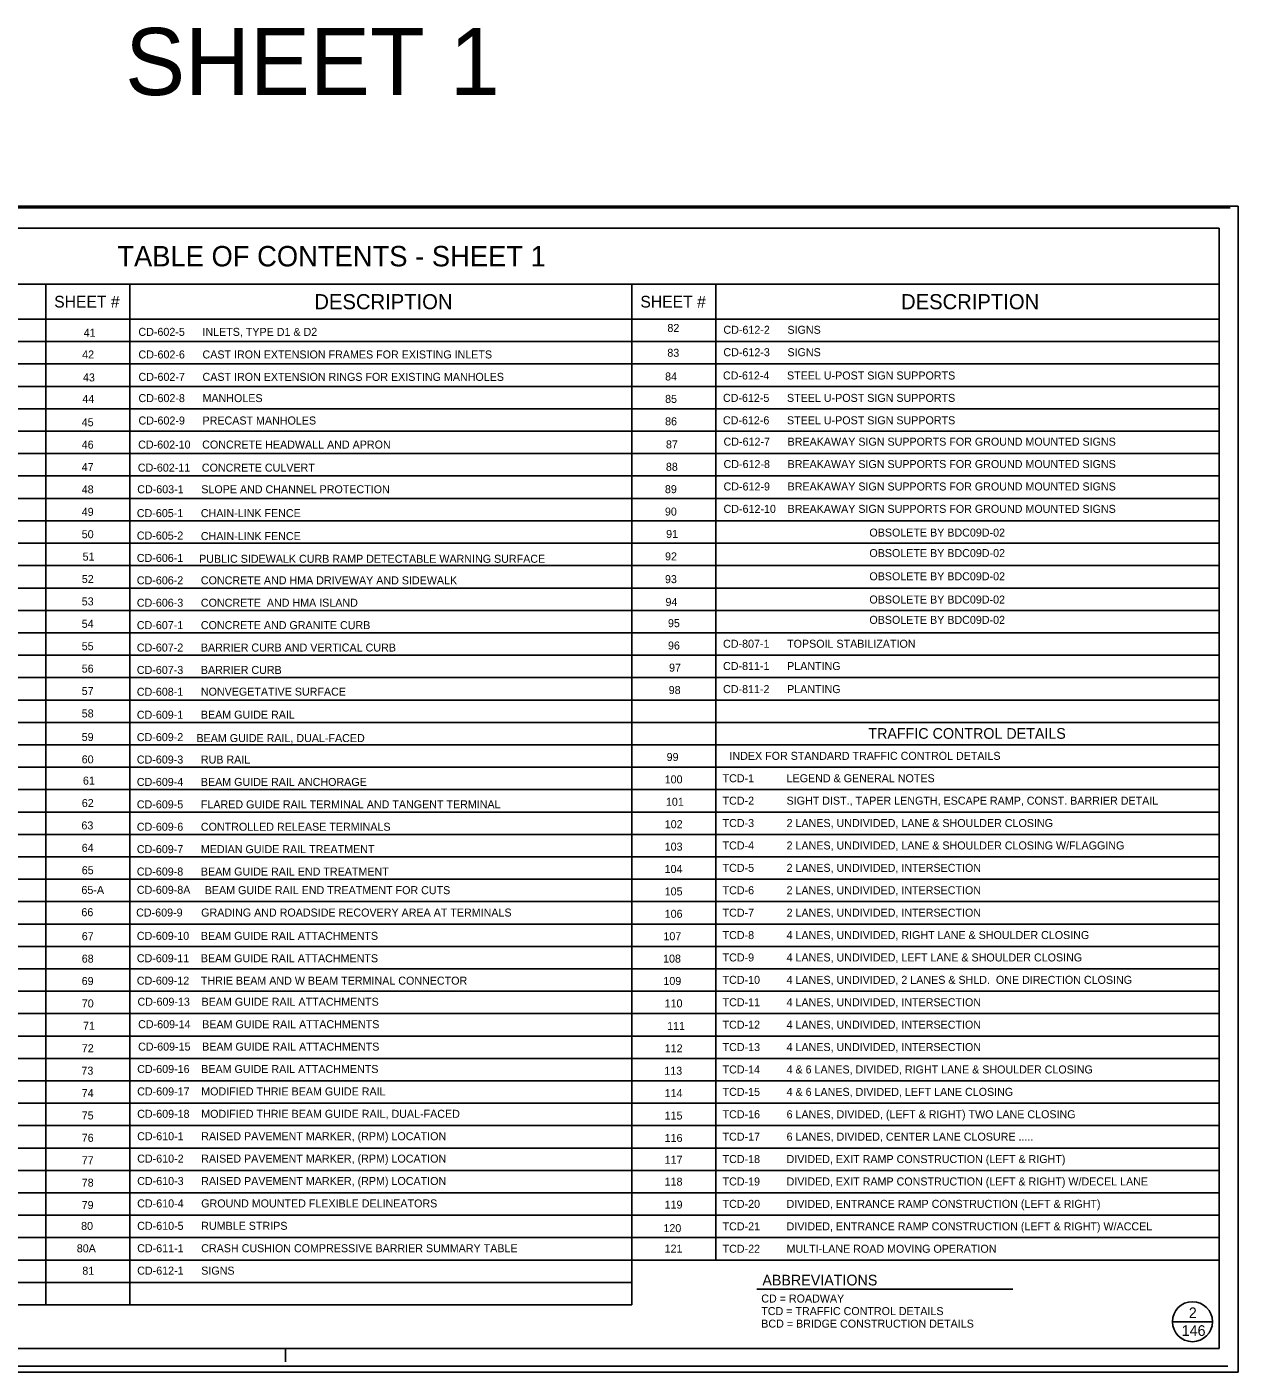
# Model space of a CAD drawing. Extents: x 499943 to 502231, y 501090 to 501849.
# Drawn here: x 500320 to 501001, y 501092 to 501849 of the extents above; entities that cross this region are included whole.
import ezdxf

# ---------------------------------------------------------------- set-up
doc = ezdxf.new("R2010")
doc.units = 0
for name, color, linetype in [('1', 7, 'Continuous'), ('39', 7, 'Continuous'), ('41', 7, 'Continuous')]:
    doc.layers.add(name, color=color, linetype=linetype)

msp = doc.modelspace()

# ---------------------------------------------------------------- linework, layer by layer
at = {"layer": '1'}
for p, q in [((500996.15, 501746.75), (499947.98, 501746.75)), ((500990, 501735.32), (500000, 501735.32)), ((500990, 501105.32), (500990, 501735.32)), ((500330.18, 501703.82), (500047.24, 501703.82)), ((500330.18, 501703.82), (500330.18, 501129.81)), ((500377.42, 501703.82), (500330.18, 501703.82)), ((500377.42, 501703.82), (500377.42, 501129.81)), ((500659.82, 501703.82), (500377.42, 501703.82)), ((500707.07, 501703.82), (500659.82, 501703.82)), ((500659.82, 501129.81), (500659.82, 501703.82)), ((500990, 501703.82), (500707.07, 501703.82)), ((500707.07, 501155), (500707.07, 501703.82)), ((500990, 501684.14), (500000, 501684.14)), ((500990, 501671.54), (500000, 501671.54)), ((500990, 501658.94), (500000, 501658.94)), ((500990, 501646.34), (500000, 501646.34)), ((500990, 501633.74), (500000, 501633.74)), ((500990, 501621.14), (500000, 501621.14)), ((500990, 501608.55), (500000, 501608.55)), ((500990, 501595.95), (500000, 501595.95)), ((500990, 501583.35), (500000, 501583.35)), ((500990, 501570.75), (500000, 501570.75)), ((500990, 501558.15), (500000, 501558.15)), ((500990, 501545.55), (500000, 501545.55)), ((500990, 501532.95), (500000, 501532.95)), ((500990, 501520.36), (500000, 501520.36)), ((500990, 501507.76), (500000, 501507.76)), ((500990, 501495.16), (500000, 501495.16)), ((500990, 501482.56), (500000, 501482.56)), ((500990, 501469.96), (500000, 501469.96)), ((500990, 501457.36), (500000, 501457.36)), ((500990, 501444.77), (500000, 501444.77)), ((500990, 501432.17), (500000, 501432.17)), ((500990, 501419.57), (500000, 501419.57)), ((500990, 501406.97), (500000, 501406.97)), ((500990, 501394.37), (500000, 501394.37)), ((500990, 501381.77), (500000, 501381.77)), ((500990, 501369.18), (500000, 501369.18)), ((500990, 501356.58), (500000, 501356.58)), ((500990, 501343.98), (500000, 501343.98)), ((500990, 501331.38), (500000, 501331.38)), ((500990, 501318.78), (500000, 501318.78)), ((500990, 501306.18), (500000, 501306.18)), ((500990, 501293.58), (500000, 501293.58)), ((500990, 501280.99), (500000, 501280.99)), ((500990, 501268.39), (500000, 501268.39)), ((500990, 501255.79), (500000, 501255.79)), ((500990, 501243.19), (500000, 501243.19)), ((500990, 501230.59), (500000, 501230.59)), ((500990, 501217.99), (500000, 501217.99)), ((500990, 501205.4), (500000, 501205.4)), ((500990, 501192.8), (500000, 501192.8)), ((500990, 501180.2), (500000, 501180.2)), ((500990, 501167.6), (500000, 501167.6)), ((500659.82, 501155), (500000, 501155)), ((500990, 501155), (500659.82, 501155)), ((500659.82, 501142.4), (500000, 501142.4)), ((500659.82, 501142.4), (500330.18, 501142.4)), ((500873.98, 501138.53), (500729.97, 501138.53)), ((500330.18, 501129.81), (500000, 501129.81)), ((500659.82, 501129.81), (500330.18, 501129.81)), ((500975, 501120.32), (500963.75, 501120.32)), ((500975, 501120.32), (500986.25, 501120.32)), ((500000, 501105.32), (500990, 501105.32)), ((500465, 501097.82), (500465, 501105.32)), ((500994.83, 501095.31), (499946.66, 501095.31))]:
    msp.add_line(p, q, dxfattribs=at)
msp.add_circle((500975, 501120.32), 11.25, dxfattribs=at)
at = {"layer": '41'}
msp.add_lwpolyline([(499942.7, 501091.97), (501000.67, 501091.97), (501000.67, 501747.65), (499942.7, 501747.65)], close=True, dxfattribs=at)

# ---------------------------------------------------------------- texts
at = {"layer": '1'}
for s, height, p in [('TABLE OF CONTENTS - SHEET 1', 11.5, (500370.42, 501713.82)), ('2', 6, (500972.96, 501122.32)), ('146', 6, (500968.97, 501112.32))]:
    msp.add_text(s, height=height, dxfattribs=at).set_placement(p)
at = {"layer": '39'}
for s, height, p in [('SHEET 1', 37.795, (500374.84, 501810.16)), ('SHEET #', 6.6, (500334.94, 501690.68)), ('DESCRIPTION', 8.5, (500481.23, 501689.73)), ('SHEET #', 6.6, (500664.58, 501690.68)), ('DESCRIPTION', 8.5, (500811.14, 501689.73)), ('41', 4.5, (500351.53, 501674.28)), ('CD-602-5', 4.5, (500382.3, 501674.76)), ('INLETS, TYPE D1 & D2', 4.5, (500418.3, 501674.76)), ('82', 4.5, (500679.77, 501676.96)), ('CD-612-2', 4.5, (500711.27, 501675.92)), ('SIGNS', 4.5, (500747.27, 501675.92)), ('42', 4.5, (500350.69, 501662.05)), ('CD-602-6', 4.5, (500382.34, 501662.05)), ('CAST IRON EXTENSION FRAMES FOR EXISTING INLETS', 4.5, (500418.34, 501662.05)), ('83', 4.5, (500679.73, 501662.99)), ('CD-612-3', 4.5, (500711.27, 501663.32)), ('SIGNS', 4.5, (500747.27, 501663.32)), ('43', 4.5, (500351.1, 501649.14)), ('CD-602-7', 4.5, (500382.34, 501649.45)), ('CAST IRON EXTENSION RINGS FOR EXISTING MANHOLES', 4.5, (500418.34, 501649.45)), ('84', 4.5, (500678.46, 501649.66)), ('CD-612-4', 4.5, (500711, 501650.22)), ('STEEL U-POST SIGN SUPPORTS', 4.5, (500747, 501650.22)), ('44', 4.5, (500350.76, 501637.05)), ('CD-602-8', 4.5, (500382.34, 501637.5)), ('MANHOLES', 4.5, (500418.34, 501637.5)), ('85', 4.5, (500678.47, 501637.06)), ('CD-612-5', 4.5, (500711, 501637.62)), ('STEEL U-POST SIGN SUPPORTS', 4.5, (500747, 501637.62)), ('45', 4.5, (500350.43, 501623.94)), ('CD-602-9', 4.5, (500382.34, 501624.9)), ('PRECAST MANHOLES', 4.5, (500418.34, 501624.9)), ('86', 4.5, (500678.47, 501624.46)), ('CD-612-6', 4.5, (500711, 501625.02)), ('STEEL U-POST SIGN SUPPORTS', 4.5, (500747, 501625.02)), ('46', 4.5, (500350.43, 501611.34)), ('CD-602-10', 4.5, (500382.17, 501611.37)), ('CONCRETE HEADWALL AND APRON', 4.5, (500418.17, 501611.37)), ('87', 4.5, (500678.95, 501611.48)), ('CD-612-7', 4.5, (500711.34, 501613)), ('BREAKAWAY SIGN SUPPORTS FOR GROUND MOUNTED SIGNS', 4.5, (500747.34, 501613)), ('47', 4.5, (500350.42, 501598.75)), ('CD-602-11', 4.5, (500381.98, 501598.4)), ('CONCRETE CULVERT', 4.5, (500417.98, 501598.4)), ('88', 4.5, (500678.93, 501598.88)), ('CD-612-8', 4.5, (500711.34, 501600.4)), ('BREAKAWAY SIGN SUPPORTS FOR GROUND MOUNTED SIGNS', 4.5, (500747.34, 501600.4)), ('48', 4.5, (500350.43, 501586.15)), ('CD-603-1', 4.5, (500381.65, 501586.23)), ('SLOPE AND CHANNEL PROTECTION', 4.5, (500417.65, 501586.23)), ('89', 4.5, (500678.36, 501586.29)), ('CD-612-9', 4.5, (500711.34, 501587.8)), ('BREAKAWAY SIGN SUPPORTS FOR GROUND MOUNTED SIGNS', 4.5, (500747.34, 501587.8)), ('49', 4.5, (500350.43, 501573.55)), ('90', 4.5, (500678.37, 501573.69)), ('CD-612-10', 4.5, (500711.34, 501575.21)), ('BREAKAWAY SIGN SUPPORTS FOR GROUND MOUNTED SIGNS', 4.5, (500747.34, 501575.21)), ('CD-605-1', 4.5, (500381.42, 501572.81)), ('CHAIN-LINK FENCE', 4.5, (500417.42, 501572.81)), ('50', 4.5, (500350.43, 501560.95)), ('CD-605-2', 4.5, (500381.42, 501560.21)), ('CHAIN-LINK FENCE', 4.5, (500417.42, 501559.89)), ('91', 4.5, (500679.05, 501561.09)), ('OBSOLETE BY BDC09D-02', 4.5, (500793.35, 501561.86)), ('51', 4.5, (500350.93, 501548.35)), ('CD-606-1', 4.5, (500381.42, 501547.61)), ('PUBLIC SIDEWALK CURB RAMP DETECTABLE WARNING SURFACE', 4.5, (500416.43, 501547.13)), ('92', 4.5, (500678.44, 501548.49)), ('OBSOLETE BY BDC09D-02', 4.5, (500793.35, 501550.34)), ('52', 4.5, (500350.47, 501535.75)), ('93', 4.5, (500678.4, 501535.69)), ('OBSOLETE BY BDC09D-02', 4.5, (500793.35, 501537.28)), ('CD-606-2', 4.5, (500381.42, 501535.02)), ('CONCRETE AND HMA DRIVEWAY AND SIDEWALK', 4.5, (500417.42, 501535.02)), ('53', 4.5, (500350.43, 501523.16)), ('CD-606-3', 4.5, (500381.42, 501522.42)), ('CONCRETE  AND HMA ISLAND', 4.5, (500417.42, 501522.42)), ('94', 4.5, (500678.69, 501522.86)), ('OBSOLETE BY BDC09D-02', 4.5, (500793.35, 501524.21)), ('OBSOLETE BY BDC09D-02', 4.5, (500793.35, 501512.78)), ('54', 4.5, (500350.42, 501510.56)), ('CD-607-1', 4.5, (500381.42, 501509.82)), ('CONCRETE AND GRANITE CURB', 4.5, (500417.42, 501509.82)), ('95', 4.5, (500680.08, 501510.93)), ('55', 4.5, (500350.43, 501497.96)), ('96', 4.5, (500680.08, 501498.34)), ('CD-807-1', 4.5, (500711.07, 501499.35)), ('TOPSOIL STABILIZATION', 4.5, (500747.07, 501499.35)), ('CD-607-2', 4.5, (500381.42, 501497.22)), ('BARRIER CURB AND VERTICAL CURB ', 4.5, (500417.42, 501497.22)), ('56', 4.5, (500350.43, 501485.36)), ('CD-607-3', 4.5, (500381.42, 501484.62)), ('BARRIER CURB', 4.5, (500417.42, 501484.62)), ('97', 4.5, (500680.7, 501485.91)), ('CD-811-1', 4.5, (500711.07, 501486.82)), ('PLANTING', 4.5, (500747.07, 501486.82)), ('57', 4.5, (500350.42, 501472.76)), ('CD-608-1', 4.5, (500381.42, 501472.34)), ('NONVEGETATIVE SURFACE', 4.5, (500417.42, 501472.4)), ('98', 4.5, (500680.5, 501473.31)), ('CD-811-2', 4.5, (500711.07, 501473.84)), ('PLANTING', 4.5, (500747.07, 501473.84)), ('58', 4.5, (500350.43, 501460.16)), ('CD-609-1', 4.5, (500381.42, 501459.42)), ('BEAM GUIDE RAIL', 4.5, (500417.42, 501459.48)), ('59', 4.5, (500350.4, 501446.91)), ('CD-609-2', 4.5, (500381.42, 501446.83)), ('BEAM GUIDE RAIL, DUAL-FACED', 4.5, (500414.94, 501446.31)), ('TRAFFIC CONTROL DETAILS', 6, (500792.79, 501448.15)), ('60', 4.5, (500350.42, 501434.32)), ('CD-609-3', 4.5, (500381.42, 501434.23)), ('RUB RAIL', 4.5, (500417.42, 501434.23)), ('99', 4.5, (500679.33, 501435.66)), ('INDEX FOR STANDARD TRAFFIC CONTROL DETAILS', 4.5, (500714.65, 501436.3)), ('61', 4.5, (500351.1, 501422.37)), ('100', 4.5, (500678.24, 501423.07)), ('TCD-1', 4.5, (500710.78, 501423.7)), ('LEGEND & GENERAL NOTES', 4.5, (500746.78, 501423.7)), ('CD-609-4', 4.5, (500381.42, 501421.63)), ('BEAM GUIDE RAIL ANCHORAGE', 4.5, (500417.42, 501421.63)), ('62', 4.5, (500350.47, 501409.77)), ('CD-609-5', 4.5, (500381.42, 501409.03)), ('FLARED GUIDE RAIL TERMINAL AND TANGENT TERMINAL', 4.5, (500417.42, 501409.03)), ('101', 4.5, (500678.92, 501410.47)), ('TCD-2', 4.5, (500710.78, 501411.1)), ('SIGHT DIST., TAPER LENGTH, ESCAPE RAMP, CONST. BARRIER DETAIL ', 4.5, (500746.78, 501411.1)), ('63', 4.5, (500350.25, 501397.17)), ('CD-609-6', 4.5, (500381.42, 501396.43)), ('CONTROLLED RELEASE TERMINALS', 4.5, (500417.42, 501396.43)), ('102', 4.5, (500678.28, 501397.87)), ('TCD-3', 4.5, (500710.78, 501398.51)), ('2 LANES, UNDIVIDED, LANE & SHOULDER CLOSING', 4.5, (500746.78, 501398.51)), ('64', 4.5, (500350.42, 501384.57)), ('103', 4.5, (500678.24, 501385.27)), ('TCD-4', 4.5, (500710.78, 501385.91)), ('2 LANES, UNDIVIDED, LANE & SHOULDER CLOSING W/FLAGGING', 4.5, (500746.78, 501385.91)), ('CD-609-7', 4.5, (500381.42, 501383.83)), ('MEDIAN GUIDE RAIL TREATMENT', 4.5, (500417.42, 501383.83)), ('65', 4.5, (500350.43, 501371.97)), ('CD-609-8', 4.5, (500381.42, 501371.24)), ('BEAM GUIDE RAIL END TREATMENT', 4.5, (500417.42, 501371.24)), ('104', 4.5, (500678.2, 501372.67)), ('TCD-5', 4.5, (500710.78, 501373.31)), ('2 LANES, UNDIVIDED, INTERSECTION', 4.5, (500746.78, 501373.31)), ('65-A', 4.5, (500350.27, 501360.88)), ('CD-609-8A', 4.5, (500381.42, 501360.95)), ('BEAM GUIDE RAIL END TREATMENT FOR CUTS', 4.5, (500419.59, 501360.77)), ('105', 4.5, (500678.24, 501360.07)), ('TCD-6', 4.5, (500710.78, 501360.71)), ('2 LANES, UNDIVIDED, INTERSECTION', 4.5, (500746.78, 501360.71)), ('66', 4.5, (500350.25, 501348.37)), ('CD-609-9', 4.5, (500381.06, 501348.17)), ('GRADING AND ROADSIDE RECOVERY AREA AT TERMINALS', 4.5, (500417.6, 501348.17)), ('106', 4.5, (500678.24, 501347.47)), ('TCD-7', 4.5, (500710.78, 501348.11)), ('2 LANES, UNDIVIDED, INTERSECTION', 4.5, (500746.78, 501348.11)), ('67', 4.5, (500350.45, 501334.86)), ('CD-609-10', 4.5, (500381.42, 501335.07)), ('BEAM GUIDE RAIL ATTACHMENTS', 4.5, (500417.42, 501335.07)), ('107', 4.5, (500677.53, 501334.88)), ('TCD-8', 4.5, (500710.78, 501335.51)), ('4 LANES, UNDIVIDED, RIGHT LANE & SHOULDER CLOSING', 4.5, (500746.78, 501335.51)), ('68', 4.5, (500350.43, 501322.26)), ('CD-609-11', 4.5, (500381.42, 501322.47)), ('BEAM GUIDE RAIL ATTACHMENTS', 4.5, (500417.42, 501322.47)), ('108', 4.5, (500677.33, 501322.28)), ('TCD-9', 4.5, (500710.78, 501322.92)), ('4 LANES, UNDIVIDED, LEFT LANE & SHOULDER CLOSING', 4.5, (500746.78, 501322.92)), ('69', 4.5, (500350.4, 501309.66)), ('CD-609-12', 4.5, (500381.42, 501309.87)), ('THRIE BEAM AND W BEAM TERMINAL CONNECTOR', 4.5, (500417.42, 501309.87)), ('109', 4.5, (500677.51, 501309.68)), ('TCD-10', 4.5, (500710.78, 501310.32)), ('4 LANES, UNDIVIDED, 2 LANES & SHLD.  ONE DIRECTION CLOSING', 4.5, (500746.78, 501310.32)), ('70', 4.5, (500350.46, 501297.06)), ('CD-609-13', 4.5, (500381.8, 501298.02)), ('BEAM GUIDE RAIL ATTACHMENTS', 4.5, (500417.8, 501298.02)), ('110', 4.5, (500678.21, 501297.08)), ('TCD-11', 4.5, (500710.78, 501297.72)), ('4 LANES, UNDIVIDED, INTERSECTION', 4.5, (500746.78, 501297.72)), ('71', 4.5, (500351.14, 501284.46)), ('CD-609-14', 4.5, (500382.15, 501285.37)), ('BEAM GUIDE RAIL ATTACHMENTS', 4.5, (500418.15, 501285.37)), ('111', 4.5, (500679.62, 501284.4)), ('TCD-12', 4.5, (500710.78, 501285.12)), ('4 LANES, UNDIVIDED, INTERSECTION', 4.5, (500746.78, 501285.12)), ('72', 4.5, (500350.47, 501271.86)), ('CD-609-15', 4.5, (500382.15, 501272.77)), ('BEAM GUIDE RAIL ATTACHMENTS', 4.5, (500418.15, 501272.77)), ('112', 4.5, (500678.25, 501271.8)), ('TCD-13', 4.5, (500710.78, 501272.52)), ('4 LANES, UNDIVIDED, INTERSECTION', 4.5, (500746.78, 501272.52)), ('73', 4.5, (500350.25, 501259.26)), ('CD-609-16', 4.5, (500381.62, 501260.17)), ('BEAM GUIDE RAIL ATTACHMENTS', 4.5, (500417.62, 501260.17)), ('113', 4.5, (500678.03, 501259.2)), ('TCD-14', 4.5, (500710.78, 501259.92)), ('4 & 6 LANES, DIVIDED, RIGHT LANE & SHOULDER CLOSING', 4.5, (500746.78, 501259.92)), ('74', 4.5, (500350.42, 501246.67)), ('CD-609-17', 4.5, (500381.62, 501247.57)), ('MODIFIED THRIE BEAM GUIDE RAIL', 4.5, (500417.62, 501247.57)), ('114', 4.5, (500678.2, 501246.6)), ('TCD-15', 4.5, (500710.78, 501247.32)), ('4 & 6 LANES, DIVIDED, LEFT LANE CLOSING', 4.5, (500746.78, 501247.32)), ('75', 4.5, (500350.43, 501234.07)), ('CD-609-18', 4.5, (500381.62, 501234.97)), ('MODIFIED THRIE BEAM GUIDE RAIL, DUAL-FACED', 4.5, (500417.62, 501234.97)), ('115', 4.5, (500678.21, 501234)), ('TCD-16', 4.5, (500710.78, 501234.73)), ('6 LANES, DIVIDED, (LEFT & RIGHT) TWO LANE CLOSING', 4.5, (500746.78, 501234.73)), ('76', 4.5, (500350.43, 501221.47)), ('CD-610-1', 4.5, (500381.62, 501222.37)), ('RAISED PAVEMENT MARKER, (RPM) LOCATION', 4.5, (500417.62, 501222.37)), ('116', 4.5, (500678.21, 501221.4)), ('TCD-17', 4.5, (500710.78, 501222.13)), ('6 LANES, DIVIDED, CENTER LANE CLOSURE .....', 4.5, (500746.78, 501222.13)), ('77', 4.5, (500350.45, 501208.87)), ('CD-610-2', 4.5, (500381.62, 501209.78)), ('RAISED PAVEMENT MARKER, (RPM) LOCATION', 4.5, (500417.62, 501209.78)), ('117', 4.5, (500678.23, 501209.1)), ('TCD-18', 4.5, (500710.78, 501209.53)), ('DIVIDED, EXIT RAMP CONSTRUCTION (LEFT & RIGHT)', 4.5, (500746.78, 501209.53)), ('78', 4.5, (500350.43, 501196.27)), ('CD-610-3', 4.5, (500381.62, 501197.18)), ('RAISED PAVEMENT MARKER, (RPM) LOCATION', 4.5, (500417.62, 501197.18)), ('118', 4.5, (500678.21, 501196.83)), ('TCD-19', 4.5, (500710.78, 501196.93)), ('DIVIDED, EXIT RAMP CONSTRUCTION (LEFT & RIGHT) W/DECEL LANE', 4.5, (500746.78, 501196.93)), ('79', 4.5, (500350.4, 501183.67)), ('CD-610-4', 4.5, (500381.62, 501184.58)), ('GROUND MOUNTED FLEXIBLE DELINEATORS', 4.5, (500417.62, 501184.58)), ('119', 4.5, (500678.21, 501183.89)), ('TCD-20', 4.5, (500710.78, 501184.33)), ('DIVIDED, ENTRANCE RAMP CONSTRUCTION (LEFT & RIGHT)', 4.5, (500746.78, 501184.33)), ('80', 4.5, (500350.08, 501171.92)), ('CD-610-5', 4.5, (500381.62, 501171.98)), ('RUMBLE STRIPS', 4.5, (500417.62, 501171.98)), ('120', 4.5, (500677.52, 501170.67)), ('TCD-21', 4.5, (500710.78, 501171.68)), ('DIVIDED, ENTRANCE RAMP CONSTRUCTION (LEFT & RIGHT) W/ACCEL', 4.5, (500746.78, 501171.68)), ('80A', 4.5, (500347.65, 501159.32)), ('CD-611-1', 4.5, (500381.62, 501159.38)), ('CRASH CUSHION COMPRESSIVE BARRIER SUMMARY TABLE', 4.5, (500417.62, 501159.38)), ('121', 4.5, (500678.2, 501159.17)), ('TCD-22', 4.5, (500710.78, 501159.08)), ('MULTI-LANE ROAD MOVING OPERATION', 4.5, (500746.78, 501159.08)), ('81', 4.5, (500350.76, 501146.72)), ('CD-612-1', 4.5, (500381.62, 501146.78)), ('SIGNS', 4.5, (500417.62, 501146.78)), ('ABBREVIATIONS', 6, (500733.17, 501140.71)), ('CD = ROADWAY ', 4.5, (500732.54, 501131.09)), ('TCD = TRAFFIC CONTROL DETAILS', 4.5, (500732.54, 501124.03)), ('BCD = BRIDGE CONSTRUCTION DETAILS', 4.5, (500732.54, 501116.97))]:
    msp.add_text(s, height=height, dxfattribs=at).set_placement(p)

doc.saveas('drawing.dxf')
